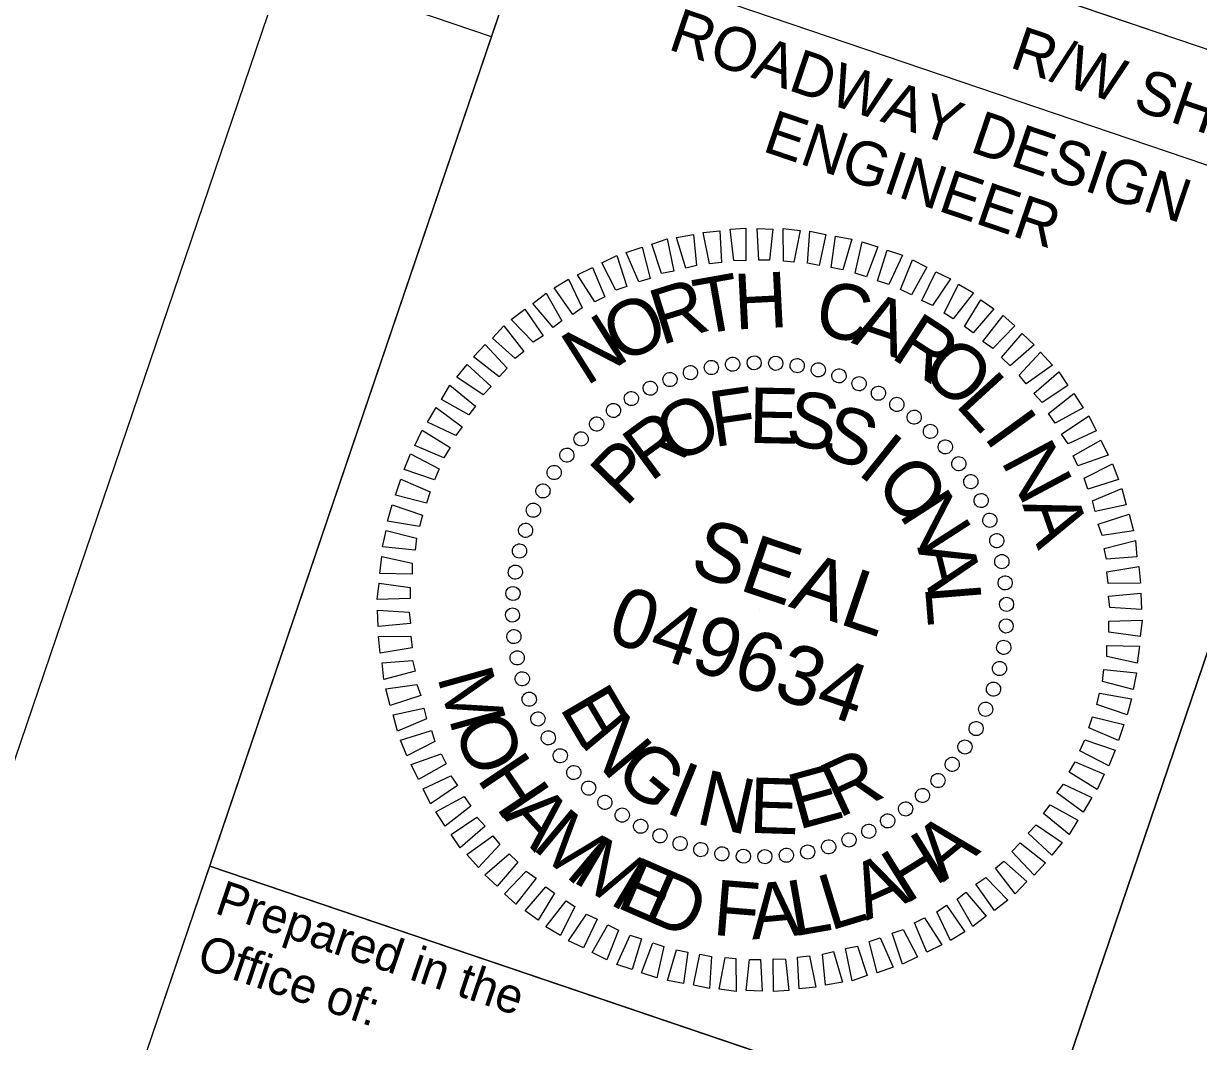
# Model space of a CAD drawing. Extents: x 2298691 to 2299860, y 598939 to 599889.
# Drawn here: x 2299689.8 to 2299770.4, y 599494.4 to 599564.2 of the extents above; entities that cross this region are included whole.
import ezdxf

# ---------------------------------------------------------------- set-up
doc = ezdxf.new("R2010")
doc.units = 0
for name, color, linetype in [('Default', 7, 'Continuous'), ('Prop DSN Text', 7, 'Continuous'), ('Scratch_Level_0', 7, 'Continuous'), ('Sheet Block Title CELL', 7, 'Continuous'), ('Sheet Border Standard 30in CELL', 7, 'Continuous'), ('Sheet Layout Plan Border', 7, 'Continuous'), ('Sheet Plan Layout CELL', 7, 'Continuous'), ('Sheet Professional Seal CELL', 7, 'Continuous')]:
    doc.layers.add(name, color=color, linetype=linetype)

# ---------------------------------------------------------------- blocks, each defined once
blk = doc.blocks.new('POINT_DISPLAY')
at = {"layer": 'Default'}
blk.add_line((0, 0), (0, 0), dxfattribs=at)

msp = doc.modelspace()

# ---------------------------------------------------------------- linework, layer by layer
at = {"layer": 'Scratch_Level_0'}
msp.add_lwpolyline([(2299002.403, 599823.524), (2298809.463, 599255.407), (2299633.245, 598975.617), (2299795.103, 599452.239), (2299681.456, 599490.838), (2299712.532, 599582.335)], close=True, dxfattribs=at)
at = {"layer": 'Sheet Block Title CELL'}
msp.add_lwpolyline([(2299702.605, 599506.467), (2299816.231, 599467.875), (2299811.166, 599452.962), (2299697.54, 599491.554)], close=True, dxfattribs=at)
at = {"layer": 'Sheet Border Standard 30in CELL'}
msp.add_line((2299726.725, 599577.483), (2299840.379, 599538.881), dxfattribs=at)
msp.add_line((2299726.725, 599577.483), (2299840.379, 599538.881), dxfattribs=at)
for points in [[(2299731.559, 599591.714), (2299845.212, 599553.113), (2299840.379, 599538.881), (2299726.725, 599577.483)], [(2299724.313, 599570.381), (2299781.154, 599551.075), (2299759.446, 599487.161), (2299702.605, 599506.467)], [(2299781.154, 599551.075), (2299837.967, 599531.779), (2299816.259, 599467.865), (2299759.446, 599487.161)]]:
    msp.add_lwpolyline(points, close=True, dxfattribs=at)
at = {"layer": 'Sheet Layout Plan Border'}
msp.add_lwpolyline([(2299035.493, 599796.458), (2298855.433, 599254.004), (2299623.37, 598993.181), (2299776.096, 599442.853), (2299690.835, 599471.811), (2299700.483, 599500.217), (2299721.915, 599563.321), (2299035.493, 599796.458)], close=True, dxfattribs=at)
at = {"layer": 'Sheet Plan Layout CELL'}
msp.add_lwpolyline([(2298993.024, 599842.551), (2298790.436, 599246.028), (2299642.625, 598956.59), (2299806.65, 599439.597), (2299693.006, 599478.203), (2299731.559, 599591.714)], close=True, dxfattribs=at)
at = {"layer": 'Sheet Professional Seal CELL'}
for points in [[(2299738.511, 599547.986), (2299738.277, 599550.132), (2299739.334, 599550.202), (2299739.353, 599547.948)], [(2299740.229, 599548.007), (2299740.113, 599550.185), (2299741.202, 599550.137), (2299740.976, 599548.003)], [(2299741.915, 599547.934), (2299741.896, 599550.186), (2299743.059, 599550.041), (2299742.64, 599547.866)], [(2299733.574, 599547.095), (2299732.901, 599549.106), (2299733.95, 599549.463), (2299734.407, 599547.24)], [(2299735.23, 599547.459), (2299734.591, 599549.565), (2299735.766, 599549.773), (2299735.967, 599547.637)], [(2299736.865, 599547.76), (2299736.418, 599549.907), (2299737.561, 599550.019), (2299737.677, 599547.841)], [(2299743.58, 599547.797), (2299743.72, 599549.995), (2299744.819, 599549.765), (2299744.38, 599547.632)], [(2299745.19, 599547.5), (2299745.491, 599549.643), (2299746.6, 599549.445), (2299745.99, 599547.335)], [(2299732.022, 599546.516), (2299731.137, 599548.529), (2299732.229, 599548.907), (2299732.782, 599546.758)], [(2299746.842, 599547.117), (2299747.325, 599549.27), (2299748.38, 599548.912), (2299747.61, 599546.856)], [(2299748.378, 599546.595), (2299749.019, 599548.695), (2299750.073, 599548.337), (2299749.144, 599546.335)], [(2299730.439, 599545.949), (2299729.468, 599547.812), (2299730.495, 599548.319), (2299731.198, 599546.191)], [(2299749.954, 599545.988), (2299750.755, 599548.033), (2299751.755, 599547.516), (2299750.688, 599545.632)], [(2299728.994, 599545.157), (2299727.798, 599546.99), (2299728.826, 599547.495), (2299729.679, 599545.495)], [(2299751.412, 599545.243), (2299752.362, 599547.203), (2299753.373, 599546.716), (2299752.146, 599544.887)], [(2299727.483, 599544.279), (2299726.213, 599546.102), (2299727.199, 599546.693), (2299728.138, 599544.735)], [(2299752.933, 599544.37), (2299753.927, 599546.35), (2299754.936, 599545.757), (2299753.551, 599543.982)], [(2299726.144, 599543.38), (2299724.744, 599545.031), (2299725.667, 599545.753), (2299726.733, 599543.856)], [(2299754.336, 599543.465), (2299755.457, 599545.295), (2299756.35, 599544.671), (2299754.932, 599543.013)], [(2299724.772, 599542.383), (2299723.265, 599543.93), (2299724.188, 599544.651), (2299725.458, 599542.828)], [(2299755.59, 599542.433), (2299756.978, 599544.209), (2299757.775, 599543.51), (2299756.282, 599541.95)], [(2299723.538, 599541.27), (2299721.976, 599542.656), (2299722.761, 599543.495), (2299724.128, 599541.747)], [(2299756.855, 599541.327), (2299758.273, 599542.985), (2299759.112, 599542.2), (2299757.45, 599540.769)], [(2299722.432, 599540.006), (2299720.689, 599541.383), (2299721.472, 599542.221), (2299722.991, 599540.601)], [(2299758.086, 599540.124), (2299759.547, 599541.696), (2299760.353, 599540.816), (2299758.563, 599539.534)], [(2299721.336, 599538.774), (2299719.538, 599539.991), (2299720.258, 599540.851), (2299721.883, 599539.336)], [(2299759.083, 599538.86), (2299760.799, 599540.344), (2299761.413, 599539.423), (2299759.656, 599538.237)], [(2299720.367, 599537.392), (2299718.483, 599538.459), (2299719.066, 599539.438), (2299720.819, 599537.987)], [(2299760.079, 599537.487), (2299761.826, 599538.854), (2299762.461, 599537.891), (2299760.533, 599536.833)], [(2299719.463, 599535.987), (2299717.524, 599536.895), (2299718.117, 599537.906), (2299719.914, 599536.583)], [(2299760.988, 599536.073), (2299762.842, 599537.333), (2299763.349, 599536.305), (2299761.444, 599535.419)], [(2299718.653, 599534.445), (2299716.662, 599535.299), (2299717.158, 599536.343), (2299719.073, 599535.158)], [(2299761.771, 599534.595), (2299763.666, 599535.662), (2299764.172, 599534.636), (2299762.108, 599533.911)], [(2299718.005, 599532.954), (2299715.927, 599533.659), (2299716.36, 599534.724), (2299718.329, 599533.698)], [(2299762.53, 599533.054), (2299764.467, 599534.036), (2299764.889, 599532.966), (2299762.772, 599532.294)], [(2299717.462, 599531.356), (2299715.33, 599531.901), (2299715.699, 599532.987), (2299717.722, 599532.122)], [(2299763.107, 599531.502), (2299765.11, 599532.356), (2299765.401, 599531.223), (2299763.285, 599530.766)], [(2299716.983, 599529.736), (2299714.797, 599530.122), (2299715.102, 599531.229), (2299717.179, 599530.524)], [(2299763.494, 599529.91), (2299765.612, 599530.582), (2299765.905, 599529.448), (2299763.767, 599529.139)], [(2299716.685, 599528.126), (2299714.444, 599528.352), (2299714.686, 599529.481), (2299716.785, 599528.947)], [(2299763.891, 599528.243), (2299766.04, 599528.796), (2299766.15, 599527.654), (2299764.067, 599527.505)], [(2299716.483, 599526.482), (2299714.253, 599526.527), (2299714.398, 599527.69), (2299716.489, 599527.23)], [(2299764.095, 599526.641), (2299766.285, 599527.001), (2299766.397, 599525.859), (2299764.176, 599525.829)], [(2299716.346, 599524.818), (2299714.072, 599524.735), (2299714.206, 599525.866), (2299716.35, 599525.566)], [(2299764.203, 599524.963), (2299766.414, 599525.175), (2299766.46, 599524.055), (2299764.295, 599524.184)], [(2299716.369, 599523.099), (2299714.158, 599522.887), (2299714.11, 599524.009), (2299716.277, 599523.878)], [(2299764.224, 599523.245), (2299766.5, 599523.328), (2299766.364, 599522.197), (2299764.221, 599522.498)], [(2299716.477, 599521.423), (2299714.286, 599521.061), (2299714.175, 599522.205), (2299716.396, 599522.234)], [(2299764.087, 599521.581), (2299766.318, 599521.536), (2299766.173, 599520.373), (2299764.083, 599520.832)], [(2299716.681, 599519.82), (2299714.532, 599519.266), (2299714.421, 599520.409), (2299716.503, 599520.558)], [(2299763.886, 599519.938), (2299766.126, 599519.712), (2299765.886, 599518.581), (2299763.785, 599519.116)], [(2299717.077, 599518.152), (2299714.96, 599517.482), (2299714.667, 599518.614), (2299716.804, 599518.923)], [(2299763.589, 599518.327), (2299765.775, 599517.941), (2299765.47, 599516.833), (2299763.392, 599517.538)], [(2299717.463, 599516.56), (2299715.462, 599515.707), (2299715.169, 599516.84), (2299717.285, 599517.297)], [(2299763.11, 599516.707), (2299765.242, 599516.161), (2299764.873, 599515.075), (2299762.85, 599515.94)], [(2299718.042, 599515.009), (2299716.104, 599514.027), (2299715.683, 599515.097), (2299717.8, 599515.768)], [(2299762.567, 599515.109), (2299764.645, 599514.403), (2299764.212, 599513.339), (2299762.243, 599514.364)], [(2299718.801, 599513.467), (2299716.906, 599512.4), (2299716.399, 599513.428), (2299718.464, 599514.153)], [(2299761.918, 599513.618), (2299763.91, 599512.764), (2299763.412, 599511.721), (2299761.498, 599512.906)], [(2299719.583, 599511.99), (2299717.728, 599510.73), (2299717.223, 599511.758), (2299719.128, 599512.643)], [(2299761.109, 599512.075), (2299763.046, 599511.168), (2299762.453, 599510.156), (2299760.657, 599511.479)], [(2299720.493, 599510.575), (2299718.746, 599509.208), (2299718.11, 599510.173), (2299720.037, 599511.23)], [(2299760.204, 599510.672), (2299762.087, 599509.604), (2299761.506, 599508.625), (2299759.752, 599510.076)], [(2299721.488, 599509.204), (2299719.772, 599507.718), (2299719.158, 599508.64), (2299720.916, 599509.825)], [(2299759.236, 599509.288), (2299761.032, 599508.073), (2299760.313, 599507.211), (2299758.688, 599508.726)], [(2299722.484, 599507.938), (2299721.024, 599506.367), (2299720.219, 599507.247), (2299722.008, 599508.528)], [(2299758.14, 599508.056), (2299759.883, 599506.681), (2299759.098, 599505.841), (2299757.581, 599507.463)], [(2299723.716, 599506.735), (2299722.298, 599505.078), (2299721.459, 599505.862), (2299723.122, 599507.294)], [(2299757.033, 599506.793), (2299758.594, 599505.406), (2299757.811, 599504.568), (2299756.444, 599506.315)], [(2299724.98, 599505.629), (2299723.593, 599503.855), (2299722.797, 599504.552), (2299724.29, 599506.114)], [(2299726.234, 599504.597), (2299725.114, 599502.767), (2299724.22, 599503.392), (2299725.639, 599505.049)], [(2299755.8, 599505.679), (2299757.307, 599504.133), (2299756.384, 599503.413), (2299755.114, 599505.234)], [(2299754.427, 599504.683), (2299755.826, 599503.031), (2299754.905, 599502.311), (2299753.837, 599504.207)], [(2299727.637, 599503.692), (2299726.645, 599501.712), (2299725.634, 599502.306), (2299727.021, 599504.08)], [(2299753.088, 599503.783), (2299754.359, 599501.962), (2299753.373, 599501.369), (2299752.434, 599503.329)], [(2299729.16, 599502.819), (2299728.21, 599500.861), (2299727.197, 599501.346), (2299728.425, 599503.175)], [(2299751.578, 599502.906), (2299752.773, 599501.074), (2299751.746, 599500.567), (2299750.893, 599502.568)], [(2299730.618, 599502.074), (2299729.816, 599500.029), (2299728.816, 599500.547), (2299729.883, 599502.432)], [(2299750.132, 599502.113), (2299751.104, 599500.25), (2299750.075, 599499.744), (2299749.373, 599501.873)], [(2299732.195, 599501.468), (2299731.553, 599499.369), (2299730.499, 599499.727), (2299731.427, 599501.729)], [(2299733.729, 599500.947), (2299733.247, 599498.793), (2299732.193, 599499.152), (2299732.962, 599501.208)], [(2299748.549, 599501.546), (2299749.435, 599499.534), (2299748.343, 599499.156), (2299747.79, 599501.304)], [(2299735.381, 599500.564), (2299735.081, 599498.419), (2299733.972, 599498.618), (2299734.582, 599500.728)], [(2299736.991, 599500.266), (2299736.85, 599498.068), (2299735.753, 599498.299), (2299736.192, 599500.431)], [(2299738.656, 599500.128), (2299738.675, 599497.876), (2299737.513, 599498.021), (2299737.93, 599500.197)], [(2299743.706, 599500.302), (2299744.153, 599498.155), (2299743.009, 599498.044), (2299742.894, 599500.222)], [(2299745.341, 599500.603), (2299745.98, 599498.497), (2299744.805, 599498.29), (2299744.603, 599500.426)], [(2299746.998, 599500.967), (2299747.669, 599498.957), (2299746.621, 599498.599), (2299746.164, 599500.823)], [(2299740.342, 599500.055), (2299740.458, 599497.877), (2299739.369, 599497.925), (2299739.594, 599500.059)], [(2299742.061, 599500.078), (2299742.294, 599497.93), (2299741.237, 599497.862), (2299741.217, 599500.115)]]:
    msp.add_lwpolyline(points, close=True, dxfattribs=at)
for centre, major_axis in [((2299738.443, 599540.87), (-0.053, 0.483)), ((2299739.917, 599540.967), (-0.011, 0.486)), ((2299741.394, 599540.934), (0.032, 0.485)), ((2299742.862, 599540.773), (0.074, 0.48)), ((2299735.548, 599540.295), (-0.136, 0.467)), ((2299736.983, 599540.646), (-0.095, 0.477)), ((2299744.311, 599540.485), (0.116, 0.472)), ((2299745.729, 599540.071), (0.156, 0.46)), ((2299732.797, 599539.226), (-0.215, 0.436)), ((2299734.149, 599539.82), (-0.176, 0.453)), ((2299747.106, 599539.536), (0.196, 0.445)), ((2299731.502, 599538.515), (-0.252, 0.416)), ((2299748.43, 599538.882), (0.234, 0.426)), ((2299730.274, 599537.695), (-0.287, 0.392)), ((2299749.693, 599538.115), (0.27, 0.404)), ((2299729.122, 599536.77), (-0.32, 0.366)), ((2299750.884, 599537.242), (0.304, 0.379)), ((2299751.995, 599536.268), (0.336, 0.351)), ((2299728.054, 599535.749), (-0.351, 0.336)), ((2299753.016, 599535.201), (0.366, 0.32)), ((2299727.08, 599534.639), (-0.379, 0.304)), ((2299753.94, 599534.048), (0.392, 0.287)), ((2299726.207, 599533.448), (-0.404, 0.27)), ((2299754.761, 599532.82), (0.416, 0.252)), ((2299725.44, 599532.185), (-0.426, 0.234)), ((2299755.471, 599531.525), (0.436, 0.215)), ((2299724.787, 599530.86), (-0.445, 0.196)), ((2299724.251, 599529.484), (-0.46, 0.156)), ((2299756.066, 599530.173), (0.453, 0.176)), ((2299756.54, 599528.774), (0.467, 0.136)), ((2299723.837, 599528.066), (-0.472, 0.116)), ((2299756.891, 599527.339), (0.477, 0.095)), ((2299723.549, 599526.617), (-0.48, 0.074)), ((2299757.116, 599525.879), (0.483, 0.053)), ((2299723.388, 599525.148), (-0.485, 0.032)), ((2299757.212, 599524.405), (0.486, 0.011)), ((2299723.356, 599523.672), (-0.486, -0.011)), ((2299757.18, 599522.928), (0.485, -0.032)), ((2299723.452, 599522.198), (-0.483, -0.053)), ((2299757.019, 599521.46), (0.48, -0.074)), ((2299723.676, 599520.738), (-0.477, -0.095)), ((2299756.73, 599520.011), (0.472, -0.116)), ((2299724.027, 599519.303), (-0.467, -0.136)), ((2299756.317, 599518.593), (0.46, -0.156)), ((2299724.502, 599517.904), (-0.453, -0.176)), ((2299725.097, 599516.552), (-0.436, -0.215)), ((2299755.781, 599517.216), (0.445, -0.196)), ((2299755.127, 599515.892), (0.426, -0.234)), ((2299725.807, 599515.257), (-0.416, -0.252)), ((2299754.361, 599514.629), (0.404, -0.27)), ((2299726.627, 599514.028), (-0.392, -0.287)), ((2299753.487, 599513.438), (0.379, -0.304)), ((2299727.552, 599512.876), (-0.366, -0.32)), ((2299728.573, 599511.809), (-0.336, -0.351)), ((2299752.513, 599512.328), (0.351, -0.336)), ((2299751.446, 599511.306), (0.32, -0.366)), ((2299729.683, 599510.835), (-0.304, -0.379)), ((2299750.294, 599510.382), (0.287, -0.392)), ((2299730.875, 599509.961), (-0.27, -0.404)), ((2299749.066, 599509.561), (0.252, -0.416)), ((2299732.137, 599509.195), (-0.234, -0.426)), ((2299733.462, 599508.541), (-0.196, -0.445)), ((2299747.77, 599508.851), (0.215, -0.436)), ((2299734.839, 599508.006), (-0.156, -0.46)), ((2299745.019, 599507.782), (0.136, -0.467)), ((2299746.418, 599508.256), (0.176, -0.453)), ((2299736.257, 599507.592), (-0.116, -0.472)), ((2299737.705, 599507.304), (-0.074, -0.48)), ((2299739.174, 599507.143), (-0.032, -0.485)), ((2299740.65, 599507.11), (0.011, -0.486)), ((2299742.124, 599507.206), (0.053, -0.483)), ((2299743.584, 599507.431), (0.095, -0.477))]:
    msp.add_ellipse(centre, major_axis=major_axis, ratio=0.999708, dxfattribs=at)

# ---------------------------------------------------------------- block references
at = {"layer": 'Sheet Professional Seal CELL', "xscale": 41.411959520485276, "yscale": 41.41195952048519, "rotation": -18.759147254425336}
for p in [(2299736.985, 599540.661), (2299738.449, 599540.877), (2299739.912, 599540.985), (2299741.396, 599540.945), (2299742.867, 599540.765), (2299744.307, 599540.491), (2299734.142, 599539.844), (2299735.542, 599540.295), (2299745.735, 599540.076), (2299732.793, 599539.232), (2299747.12, 599539.536), (2299748.429, 599538.876), (2299731.486, 599538.535), (2299749.706, 599538.123), (2299730.275, 599537.699), (2299750.908, 599537.25), (2299729.107, 599536.776), (2299728.044, 599535.746), (2299752.002, 599536.274), (2299753.031, 599535.211), (2299727.066, 599534.652), (2299753.953, 599534.042), (2299726.195, 599533.452), (2299754.789, 599532.831), (2299725.44, 599532.174), (2299724.782, 599530.865), (2299755.487, 599531.525), (2299756.098, 599530.176), (2299724.24, 599529.482), (2299756.549, 599528.775), (2299723.827, 599528.053), (2299756.915, 599527.332), (2299723.551, 599526.614), (2299757.13, 599525.867), (2299723.372, 599525.142), (2299757.24, 599524.404), (2299723.332, 599523.658), (2299740.286, 599524.032), (2299757.2, 599522.922), (2299756.745, 599520.01), (2299724.022, 599519.287), (2299756.332, 599518.582), (2299724.473, 599517.886), (2299755.79, 599517.197), (2299725.085, 599516.539), (2299755.131, 599515.888), (2299725.783, 599515.232), (2299726.619, 599514.02), (2299754.377, 599514.612), (2299753.506, 599513.41), (2299727.54, 599512.853), (2299752.528, 599512.316), (2299728.57, 599511.79), (2299729.664, 599510.812), (2299751.465, 599511.286), (2299730.866, 599509.941), (2299750.296, 599510.364), (2299732.142, 599509.186), (2299749.085, 599509.527), (2299733.451, 599508.528), (2299747.779, 599508.831), (2299734.836, 599507.986), (2299736.264, 599507.573), (2299745.029, 599507.768), (2299746.43, 599508.22), (2299737.704, 599507.297), (2299739.176, 599507.118), (2299740.66, 599507.077), (2299742.123, 599507.187), (2299743.586, 599507.403)]:
    msp.add_blockref('POINT_DISPLAY', p, dxfattribs=at)

# ---------------------------------------------------------------- texts
at = {"layer": 'Prop DSN Text'}
for s, height, p in [('Prepared in the ', 2.40001, (2299702.859, 599503.255)), ('Office of:', 2.4, (2299701.605, 599499.562))]:
    msp.add_text(s, height=height, rotation=341.24042, dxfattribs=at).set_placement(p)
at = {"layer": 'Sheet Border Standard 30in CELL'}
for s, height, p in [('ROADWAY DESIGN', 3.00007, (2299733.926, 599562.49)), ('R/W SHEET NO.', 3.00007, (2299757.333, 599561.257)), ('ENGINEER', 3.0001, (2299740.395, 599555.509))]:
    msp.add_text(s, height=height, rotation=341.24042, dxfattribs=at).set_placement(p)
at = {"layer": 'Sheet Professional Seal CELL'}
for s, height, rotation, p in [('T', 3.806, 10.06062, (2299736.167, 599542.864)), ('H', 3.806, 2.86033, (2299738.613, 599543.245)), ('R', 3.806, 17.26136, (2299733.541, 599542.154)), ('C', 3.806, 348.46072, (2299743.912, 599542.979)), ('O', 3.806, 24.46259, (2299730.686, 599540.881)), ('A', 3.806, 341.26117, (2299746.515, 599542.343)), ('N', 3.806, 32.40132, (2299728.404, 599539.33)), ('R', 3.806, 326.86195, (2299749.174, 599541.367)), ('O', 3.806, 319.66202, (2299751.166, 599540.189)), ('L', 3.806, 312.46173, (2299753.618, 599538.073)), ('F', 3.807, 8.20789, (2299737.153, 599535.183)), ('E', 3.807, 358.85192, (2299739.536, 599535.479)), ('S', 3.807, 349.49646, (2299741.951, 599535.444)), ('O', 3.807, 26.92209, (2299734.436, 599533.975)), ('R', 3.807, 36.2805, (2299732.804, 599532.746)), ('S', 3.807, 340.14125, (2299744.275, 599534.726)), ('I', 3.806, 306.02142, (2299755.581, 599535.919)), ('I', 3.807, 321.43046, (2299746.897, 599533.406)), ('N', 3.806, 298.05976, (2299756.774, 599534.257)), ('P', 3.807, 45.63974, (2299731.105, 599531.004)), ('O', 3.807, 312.07434, (2299748.058, 599532.509)), ('N', 3.807, 302.71746, (2299749.782, 599530.571)), ('A', 3.806, 289.30297, (2299758.267, 599531.262)), ('SEAL', 4.0496, 341.24085, (2299735.361, 599526.596)), ('A', 3.807, 284.00112, (2299751.084, 599528.307)), ('049634', 4.0508, 341.24085, (2299729.673, 599521.967)), ('L', 3.807, 274.6417, (2299751.611, 599525.667)), ('M', 3.807, 285.65155, (2299718.173, 599519.456)), ('E', 3.807, 300.51774, (2299726.528, 599517.333)), ('N', 3.807, 309.87481, (2299727.875, 599514.982)), ('O', 3.807, 294.74763, (2299719.198, 599515.906)), ('G', 3.807, 320.74406, (2299730.17, 599512.503)), ('H', 3.807, 303.90599, (2299720.853, 599512.466)), ('R', 3.807, 24.72226, (2299745.698, 599509.721)), ('I', 3.807, 337.94205, (2299733.7, 599510.189)), ('E', 3.807, 15.36494, (2299742.93, 599508.942)), ('N', 3.807, 347.29724, (2299735.819, 599509.398)), ('E', 3.807, 358.20772, (2299739.543, 599508.747)), ('A', 3.807, 311.79, (2299722.631, 599509.884)), ('M', 3.807, 320.16627, (2299724.605, 599507.714)), ('A', 3.807, 39.11914, (2299752.886, 599505.329)), ('M', 3.807, 329.25725, (2299727.349, 599505.456)), ('H', 3.807, 31.92395, (2299750.304, 599503.81)), ('E', 3.807, 336.38391, (2299730.362, 599503.684)), ('A', 3.807, 24.11968, (2299747.615, 599502.703)), ('D', 3.807, 336.38391, (2299732.193, 599502.889)), ('L', 3.807, 16.93441, (2299745.113, 599502.021)), ('F', 3.807, 355.32362, (2299737.016, 599501.753)), ('A', 3.807, 5.22427, (2299739.777, 599501.424)), ('L', 3.807, 9.96916, (2299742.593, 599501.627))]:
    msp.add_text(s, height=height, rotation=rotation, dxfattribs=at).set_placement(p)

doc.saveas('drawing.dxf')
